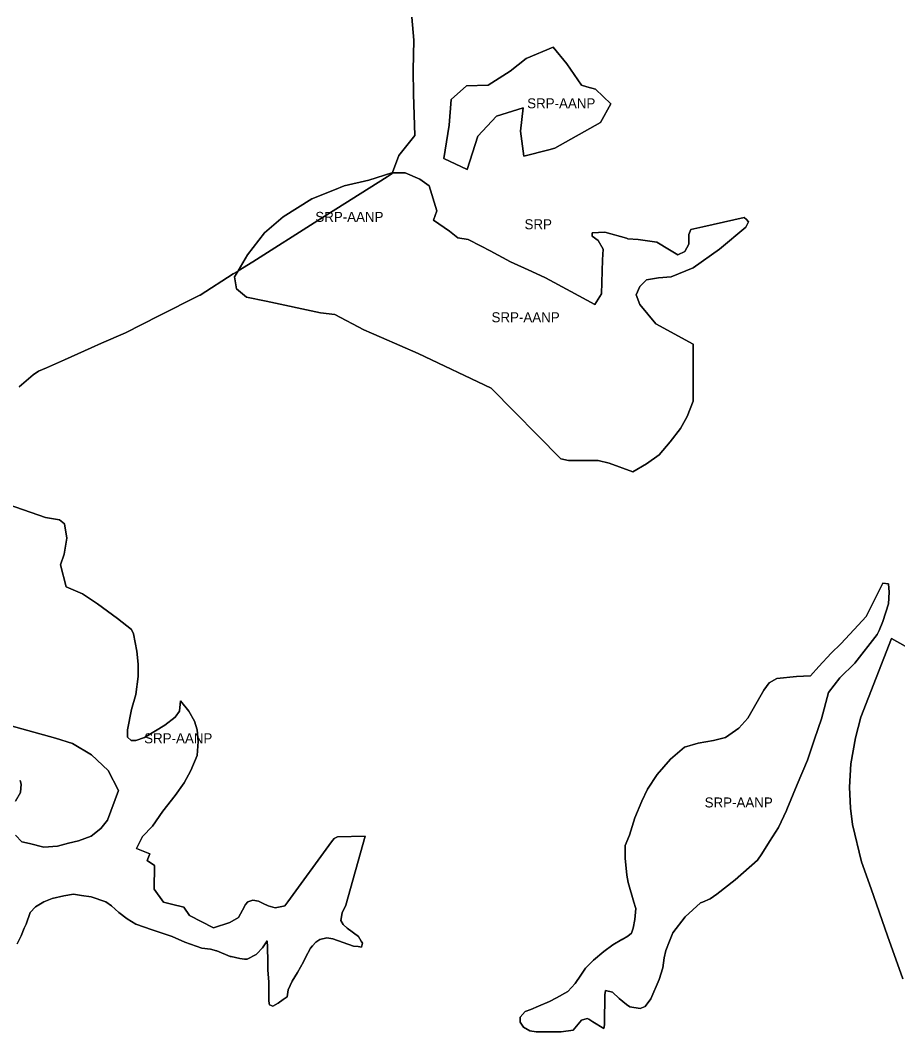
# Model space of a CAD drawing. Extents: x 598968 to 613553, y 4409678 to 4430833.
# Drawn here: x 604005 to 605061, y 4419054 to 4420271 of the extents above; entities that cross this region are included whole.
import ezdxf

# ---------------------------------------------------------------- set-up
doc = ezdxf.new("R2010")
doc.units = 0
for name, color, linetype in [('Nucli Rural', 7, 'Continuous'), ('Sòl Rústic Protegit', 7, 'Continuous'), ('Sòl Rústic Protegit - Alt Nivell de Protecció', 7, 'Continuous')]:
    doc.layers.add(name, color=color, linetype=linetype)

msp = doc.modelspace()

# ---------------------------------------------------------------- linework, layer by layer
at = {"layer": 'Nucli Rural'}
msp.add_lwpolyline([(605086.66, 4419508.7301), (605054.05, 4419527.2401), (605017.1184, 4419432.863), (605010.4212, 4419407.6728), (605004.92, 4419376.5601), (605003.39, 4419348.6024), (605004.54, 4419323.2601), (605006.9552, 4419303.6137), (605017.6511, 4419258.581), (605029.3139, 4419226.1929), (605049.202, 4419169.6187), (605067.6359, 4419117.6672)], dxfattribs=at)
at = {"layer": 'Sòl Rústic Protegit'}
for points in [[(604003.7317, 4419830.1952), (604020.6695, 4419844.6952), (604027.2321, 4419849.1952), (604036.6071, 4419853.1952), (604058.2949, 4419862.6952), (604090.4203, 4419877.1952), (604102.8579, 4419882.6954), (604132.0457, 4419895.1954), (604171.9213, 4419915.6954), (604220.7343, 4419940.1956), (604221.6719, 4419940.6956), (604261.6099, 4419966.1956), (604266.6725, 4419969.1956), (604267.4395, 4419969.6786), (604278.5549, 4419989.0102), (604298.9927, 4420015.5102), (604321.4925, 4420035.0102), (604356.2427, 4420056.5102), (604383.3051, 4420067.5102), (604395.1177, 4420072.0102), (604424.7427, 4420079.0102), (604452.3677, 4420088.0102), (604453.2509, 4420088.0102), (604453.2999, 4420088.196), (604460.8625, 4420108.696), (604480.2379, 4420132.696), (604478.3629, 4420182.6962), (604478.1131, 4420211.1962), (604478.8633, 4420247.6962), (604476.6133, 4420275.1962)], [(604476.6133, 4420275.1962), (604478.8633, 4420247.6962), (604478.1131, 4420211.1962), (604478.3629, 4420182.6962), (604480.2379, 4420132.696), (604460.8625, 4420108.696), (604453.2999, 4420088.196), (604453.2509, 4420088.0102), (604453.6799, 4420088.0102), (604468.6801, 4420088.0102), (604486.0551, 4420080.0102), (604497.3051, 4420072.0102), (604506.4925, 4420042.0102), (604502.4301, 4420031.0102), (604521.8675, 4420017.5102), (604532.0549, 4420009.5102), (604544.3677, 4420007.5102), (604559.9925, 4419999.5102), (604570.9301, 4419994.0102), (604595.4301, 4419980.5102), (604620.9301, 4419969.0102), (604637.3677, 4419961.5102), (604668.0549, 4419945.0102), (604696.6799, 4419929.5102), (604704.8049, 4419942.0102), (604705.8675, 4419983.0102), (604706.8675, 4419996.0102), (604700.7427, 4420006.5102), (604693.5549, 4420011.5102), (604693.5549, 4420015.5102), (604708.9299, 4420016.5102), (604734.9927, 4420009.0102), (604736.4927, 4420008.5102), (604748.8049, 4420007.5102), (604771.2425, 4420004.5102), (604786.6175, 4419995.0102), (604796.8051, 4419989.0102), (604804.9927, 4419993.0102), (604810.1177, 4420002.0102), (604810.1177, 4420013.5102), (604812.1801, 4420019.5102), (604826.8049, 4420023.0102), (604876.5551, 4420034.0102), (604879.2425, 4420031.5102), (604881.6799, 4420029.0102), (604878.6177, 4420022.5102), (604846.9301, 4419996.0102), (604815.2425, 4419973.5102), (604788.6799, 4419962.5102), (604773.3049, 4419961.5102), (604758.9925, 4419959.0102), (604750.8051, 4419951.0102), (604746.7425, 4419941.0102), (604750.8051, 4419929.5102), (604770.2427, 4419906.0102), (604815.2425, 4419881.5102), (604815.2425, 4419813.0102), (604808.0551, 4419794.5102), (604799.8675, 4419780.0102), (604787.6175, 4419764.0102), (604774.3675, 4419748.5102), (604758.9925, 4419737.5102), (604742.6801, 4419728.0102), (604714.0551, 4419738.5102), (604700.7427, 4419741.5102), (604684.3677, 4419741.5102), (604664.9299, 4419741.5102), (604655.7427, 4419743.5102), (604571.9299, 4419828.5102), (604484.0551, 4419870.5102), (604440.0549, 4419889.5102), (604427.8049, 4419895.0102), (604418.6177, 4419899.0102), (604383.8677, 4419917.5102), (604366.4927, 4419919.5102), (604301.0551, 4419933.5102), (604277.5551, 4419938.0102), (604265.3051, 4419948.0102), (604263.2427, 4419962.5102), (604267.0551, 4419969.0102), (604267.4395, 4419969.6786), (604266.6725, 4419969.1956), (604261.6099, 4419966.1956), (604221.6719, 4419940.6956), (604220.7343, 4419940.1956), (604171.9213, 4419915.6954), (604132.0457, 4419895.1954), (604102.8579, 4419882.6954), (604090.4203, 4419877.1952), (604058.2949, 4419862.6952), (604036.6071, 4419853.1952), (604027.2321, 4419849.1952), (604020.6695, 4419844.6952), (604003.7317, 4419830.1952)], [(603943.9927, 4419704.5102), (604035.4301, 4419673.0102), (604052.3677, 4419670.0102), (604058.6175, 4419665.5102), (604061.1177, 4419648.0102), (604057.9927, 4419629.0102), (604053.6177, 4419616.0102), (604060.4927, 4419589.5102), (604079.9299, 4419581.0102), (604098.1175, 4419569.0102), (604122.2425, 4419551.5102), (604139.1801, 4419538.0102), (604141.6801, 4419533.0102), (604145.4301, 4419512.0102), (604147.3051, 4419496.5102), (604147.3051, 4419481.5102), (604144.1801, 4419460.0102), (604139.1801, 4419442.0102), (604134.1175, 4419417.5102), (604134.1175, 4419408.5102), (604138.4927, 4419404.5102), (604144.1801, 4419404.5102), (604154.8051, 4419408.0102), (604179.2425, 4419423.0102), (604191.8049, 4419432.5102), (604196.8051, 4419440.0102), (604198.0549, 4419452.5102), (604208.0551, 4419440.0102), (604214.9299, 4419428.0102), (604218.1177, 4419417.5102), (604219.3677, 4419403.5102), (604218.1177, 4419386.5102), (604210.5551, 4419368.5102), (604202.4301, 4419353.5102), (604191.8049, 4419338.5102), (604176.7425, 4419319.5102), (604164.1799, 4419301.5102), (604152.2425, 4419289.0102), (604145.0551, 4419274.5102), (604161.2427, 4419268.0102), (604157.9299, 4419260.0102), (604166.8677, 4419254.0102), (604166.5551, 4419225.5102), (604177.6801, 4419210.0102), (604187.0551, 4419207.5102), (604202.2425, 4419204.0102), (604208.8677, 4419194.0102), (604237.9299, 4419179.0102), (604257.4301, 4419185.5102), (604267.7427, 4419191.5102), (604272.5549, 4419200.5102), (604276.1801, 4419207.0102), (604279.1799, 4419210.5102), (604285.1799, 4419212.5102), (604292.0551, 4419211.0102), (604297.7425, 4419208.5102), (604303.4301, 4419205.5102), (604311.8677, 4419203.0102), (604321.9927, 4419205.0102), (604323.5551, 4419205.5102), (604327.4299, 4419210.5102), (604379.9299, 4419282.5102), (604382.9301, 4419286.5102), (604386.8675, 4419288.5102), (604420.4301, 4419289.5102), (604397.0549, 4419206.5102), (604392.8051, 4419197.0102), (604391.0551, 4419188.0102), (604393.7427, 4419183.0102), (604398.8049, 4419178.5102), (604412.3051, 4419168.5102), (604415.6175, 4419163.0102), (604417.1177, 4419160.5102), (604415.9299, 4419156.0102), (604411.9927, 4419156.5102), (604406.3051, 4419157.0102), (604381.4927, 4419166.0102), (604374.3049, 4419167.0102), (604365.6175, 4419165.0102), (604360.8051, 4419162.0102), (604356.9301, 4419157.5102), (604354.4927, 4419154.5102), (604348.4925, 4419143.5102), (604346.1177, 4419138.0102), (604338.9301, 4419125.5102), (604332.3051, 4419115.0102), (604327.8049, 4419104.5102), (604326.3051, 4419096.0102), (604321.8051, 4419093.0102), (604315.8051, 4419088.5102), (604309.2425, 4419085.0102), (604305.3051, 4419086.5102), (604304.4299, 4419091.0102), (604304.2427, 4419108.5102), (604304.2427, 4419114.0102), (604303.3675, 4419128.0102), (604303.0551, 4419141.5102), (604302.8051, 4419153.0102), (604302.7427, 4419156.0102), (604302.2427, 4419163.5102), (604296.7425, 4419155.0102), (604290.0549, 4419148.0102), (604289.2427, 4419147.0102), (604278.1799, 4419141.5102), (604275.2427, 4419141.5102), (604269.4299, 4419142.0102), (604259.1177, 4419144.5102), (604258.3677, 4419144.5102), (604257.9927, 4419144.5102), (604241.7427, 4419151.5102), (604241.5551, 4419151.5102), (604234.0551, 4419153.5102), (604223.5551, 4419154.5102), (604203.1801, 4419162.0102), (604187.8677, 4419168.5102), (604163.8675, 4419176.5102), (604144.4927, 4419183.5102), (604133.9927, 4419190.0102), (604123.7427, 4419197.5102), (604115.0551, 4419205.5102), (604108.1799, 4419210.5102), (604090.4927, 4419216.5102), (604079.0551, 4419218.0102), (604069.1801, 4419219.5102), (604057.4925, 4419217.5102), (604043.6801, 4419214.5102), (604033.4927, 4419210.5102), (604023.5551, 4419204.5102), (604017.3049, 4419197.5102), (604012.2427, 4419183.5102), (604009.8051, 4419178.5102), (604006.3051, 4419169.5102), (604005.6177, 4419168.0102), (604001.4301, 4419160.0102)], [(605067.6359, 4419117.6672), (605049.202, 4419169.6187), (605029.3139, 4419226.1929), (605017.6511, 4419258.581), (605006.9552, 4419303.6137), (605004.54, 4419323.2601), (605003.39, 4419348.6024), (605004.92, 4419376.5601), (605010.4212, 4419407.6728), (605017.1184, 4419432.863), (605054.05, 4419527.2401), (605086.66, 4419508.7301)], [(603999.3051, 4419290.5102), (604007.1177, 4419282.5102), (604016.4301, 4419280.5102), (604033.4927, 4419276.0102), (604049.9927, 4419277.5102), (604063.1801, 4419281.0102), (604075.4927, 4419284.0102), (604090.4927, 4419289.5102), (604102.1177, 4419298.5102), (604110.2427, 4419308.5102), (604123.3677, 4419344.5102), (604110.8677, 4419368.5102), (604090.8051, 4419387.5102), (604068.2427, 4419401.0102), (604047.5551, 4419407.5102), (603980.5549, 4419426.0102)], [(604004.9927, 4419356.5102), (604006.2427, 4419352.0102), (604005.6177, 4419342.0102), (603999.3677, 4419331.5102)]]:
    msp.add_lwpolyline(points, dxfattribs=at)
for points in [[(604715.8677, 4420171.0098), (604703.6177, 4420148.5098), (604648.7427, 4420117.5098), (604641.3677, 4420115.5098), (604611.3051, 4420108.0098), (604607.3677, 4420138.0098), (604610.5551, 4420166.0098), (604578.2427, 4420156.0098), (604555.8051, 4420132.0098), (604543.3051, 4420092.0098), (604514.8677, 4420105.0098), (604521.6177, 4420145.0098), (604524.0551, 4420176.0098), (604542.2427, 4420192.5098), (604568.3677, 4420193.5098), (604594.8677, 4420210.0098), (604614.3051, 4420225.5098), (604646.5551, 4420239.0098), (604662.9927, 4420219.0098), (604680.8677, 4420193.5098), (604687.1177, 4420191.5098), (604697.6177, 4420188.5098)], [(604774.4301, 4419117.0102), (604764.1177, 4419093.5102), (604757.2425, 4419084.5102), (604751.2425, 4419082.0102), (604738.8051, 4419084.0102), (604734.9301, 4419087.0102), (604725.9301, 4419094.0102), (604718.2427, 4419101.5102), (604709.6799, 4419103.5102), (604708.8051, 4419098.5102), (604708.8051, 4419088.5102), (604708.3677, 4419074.5102), (604708.3677, 4419062.5102), (604707.4927, 4419058.0102), (604694.2425, 4419066.0102), (604689.4299, 4419069.0102), (604687.3677, 4419070.0102), (604680.9301, 4419068.0102), (604676.6801, 4419063.0102), (604670.6801, 4419056.0102), (604656.1175, 4419054.0102), (604638.5551, 4419054.0102), (604626.1175, 4419054.0102), (604618.4299, 4419055.0102), (604611.1177, 4419059.5102), (604606.8675, 4419065.5102), (604607.0551, 4419071.5102), (604612.9301, 4419078.5102), (604619.7427, 4419081.0102), (604629.1177, 4419085.0102), (604642.3677, 4419090.5102), (604650.6175, 4419095.0102), (604664.1799, 4419102.5102), (604672.9925, 4419112.0102), (604679.8051, 4419122.0102), (604685.6801, 4419130.5102), (604695.1177, 4419140.0102), (604707.4301, 4419150.5102), (604718.3675, 4419158.5102), (604729.2425, 4419165.0102), (604729.5549, 4419165.0102), (604736.6801, 4419169.0102), (604740.9301, 4419172.5102), (604742.9927, 4419178.5102), (604745.1177, 4419189.0102), (604745.5551, 4419198.0102), (604745.9925, 4419202.5102), (604745.6177, 4419203.5102), (604743.8051, 4419210.0102), (604737.0551, 4419233.5102), (604735.3677, 4419242.5102), (604733.1801, 4419263.0102), (604733.1801, 4419278.0102), (604738.3675, 4419290.5102), (604745.0551, 4419311.5102), (604753.4301, 4419331.5102), (604760.1801, 4419346.0102), (604771.9299, 4419363.5102), (604787.8051, 4419382.0102), (604804.6177, 4419396.5102), (604821.3677, 4419401.5102), (604839.8051, 4419404.5102), (604853.9927, 4419408.0102), (604869.9301, 4419419.5102), (604880.8051, 4419431.5102), (604900.1177, 4419465.0102), (604906.8051, 4419474.0102), (604916.0551, 4419479.0102), (604939.4927, 4419481.5102), (604947.9927, 4419482.0102), (604956.3051, 4419482.5102), (604966.3675, 4419493.5102), (604966.5551, 4419493.5102), (604981.4301, 4419509.5102), (604992.8051, 4419521.0102), (605009.1177, 4419538.0102), (605023.3675, 4419554.0102), (605043.4927, 4419594.0102), (605050.1801, 4419593.0102), (605051.0551, 4419583.0102), (605050.1801, 4419569.0102), (605043.4927, 4419548.0102), (605038.8677, 4419537.0102), (605036.8051, 4419532.0102), (605009.9301, 4419497.5102), (604991.4925, 4419480.0102), (604978.1177, 4419462.5102), (604969.6801, 4419430.5102), (604961.3051, 4419406.0102), (604952.9301, 4419381.0102), (604940.3677, 4419351.5102), (604927.8049, 4419321.5102), (604927.3677, 4419320.5102), (604917.7425, 4419300.0102), (604906.8675, 4419283.0102), (604897.6177, 4419268.0102), (604892.6177, 4419260.5102), (604865.7427, 4419237.0102), (604843.4927, 4419219.5102), (604835.6801, 4419214.0102), (604826.3677, 4419210.0102), (604823.9301, 4419209.0102), (604805.6177, 4419192.5102), (604790.6177, 4419173.0102), (604786.8677, 4419163.0102), (604782.0549, 4419152.0102), (604780.3049, 4419143.0102), (604778.6801, 4419131.0102)]]:
    msp.add_lwpolyline(points, close=True, dxfattribs=at)
at = {"layer": 'Sòl Rústic Protegit - Alt Nivell de Protecció'}
for points in [[(604715.8677, 4420171.0098), (604697.6177, 4420188.5098), (604687.1177, 4420191.5098), (604680.8677, 4420193.5098), (604662.9927, 4420219.0098), (604646.5551, 4420239.0098), (604614.3051, 4420225.5098), (604594.8677, 4420210.0098), (604568.3677, 4420193.5098), (604542.2427, 4420192.5098), (604524.0551, 4420176.0098), (604521.6177, 4420145.0098), (604514.8677, 4420105.0098), (604543.3051, 4420092.0098), (604555.8051, 4420132.0098), (604578.2427, 4420156.0098), (604610.5551, 4420166.0098), (604607.3677, 4420138.0098), (604611.3051, 4420108.0098), (604641.3677, 4420115.5098), (604648.7427, 4420117.5098), (604703.6177, 4420148.5098)], [(604267.4395, 4419969.6786), (604267.0551, 4419969.0102), (604263.2427, 4419962.5102), (604265.3051, 4419948.0102), (604277.5551, 4419938.0102), (604301.0551, 4419933.5102), (604366.4927, 4419919.5102), (604383.8677, 4419917.5102), (604418.6177, 4419899.0102), (604427.8049, 4419895.0102), (604440.0549, 4419889.5102), (604484.0551, 4419870.5102), (604571.9299, 4419828.5102), (604655.7427, 4419743.5102), (604664.9299, 4419741.5102), (604684.3677, 4419741.5102), (604700.7427, 4419741.5102), (604714.0551, 4419738.5102), (604742.6801, 4419728.0102), (604758.9925, 4419737.5102), (604774.3675, 4419748.5102), (604787.6175, 4419764.0102), (604799.8675, 4419780.0102), (604808.0551, 4419794.5102), (604815.2425, 4419813.0102), (604815.2425, 4419881.5102), (604770.2427, 4419906.0102), (604750.8051, 4419929.5102), (604746.7425, 4419941.0102), (604750.8051, 4419951.0102), (604758.9925, 4419959.0102), (604773.3049, 4419961.5102), (604788.6799, 4419962.5102), (604815.2425, 4419973.5102), (604846.9301, 4419996.0102), (604878.6177, 4420022.5102), (604881.6799, 4420029.0102), (604879.2425, 4420031.5102), (604876.5551, 4420034.0102), (604826.8049, 4420023.0102), (604812.1801, 4420019.5102), (604810.1177, 4420013.5102), (604810.1177, 4420002.0102), (604804.9927, 4419993.0102), (604796.8051, 4419989.0102), (604786.6175, 4419995.0102), (604771.2425, 4420004.5102), (604748.8049, 4420007.5102), (604736.4927, 4420008.5102), (604734.9927, 4420009.0102), (604708.9299, 4420016.5102), (604693.5549, 4420015.5102), (604693.5549, 4420011.5102), (604700.7427, 4420006.5102), (604706.8675, 4419996.0102), (604705.8675, 4419983.0102), (604704.8049, 4419942.0102), (604696.6799, 4419929.5102), (604668.0549, 4419945.0102), (604637.3677, 4419961.5102), (604620.9301, 4419969.0102), (604595.4301, 4419980.5102), (604570.9301, 4419994.0102), (604559.9925, 4419999.5102), (604544.3677, 4420007.5102), (604532.0549, 4420009.5102), (604521.8675, 4420017.5102), (604502.4301, 4420031.0102), (604506.4925, 4420042.0102), (604497.3051, 4420072.0102), (604486.0551, 4420080.0102), (604468.6801, 4420088.0102), (604453.6799, 4420088.0102), (604453.2509, 4420088.0102), (604453.0133, 4420087.1104), (604446.7853, 4420083.1674), (604363.4083, 4420030.3798), (604285.0179, 4419980.7492)], [(604267.4395, 4419969.6786), (604285.0179, 4419980.7492), (604363.4083, 4420030.3798), (604446.7853, 4420083.1674), (604453.0133, 4420087.1104), (604453.2509, 4420088.0102), (604452.3677, 4420088.0102), (604424.7427, 4420079.0102), (604395.1177, 4420072.0102), (604383.3051, 4420067.5102), (604356.2427, 4420056.5102), (604321.4925, 4420035.0102), (604298.9927, 4420015.5102), (604278.5549, 4419989.0102)], [(604774.4301, 4419117.0102), (604778.6801, 4419131.0102), (604780.3049, 4419143.0102), (604782.0549, 4419152.0102), (604786.8677, 4419163.0102), (604790.6177, 4419173.0102), (604805.6177, 4419192.5102), (604823.9301, 4419209.0102), (604826.3677, 4419210.0102), (604835.6801, 4419214.0102), (604843.4927, 4419219.5102), (604865.7427, 4419237.0102), (604892.6177, 4419260.5102), (604897.6177, 4419268.0102), (604906.8675, 4419283.0102), (604917.7425, 4419300.0102), (604927.3677, 4419320.5102), (604927.8049, 4419321.5102), (604940.3677, 4419351.5102), (604952.9301, 4419381.0102), (604961.3051, 4419406.0102), (604969.6801, 4419430.5102), (604978.1177, 4419462.5102), (604991.4925, 4419480.0102), (605009.9301, 4419497.5102), (605036.8051, 4419532.0102), (605038.8677, 4419537.0102), (605043.4927, 4419548.0102), (605050.1801, 4419569.0102), (605051.0551, 4419583.0102), (605050.1801, 4419593.0102), (605043.4927, 4419594.0102), (605023.3675, 4419554.0102), (605009.1177, 4419538.0102), (604992.8051, 4419521.0102), (604981.4301, 4419509.5102), (604966.5551, 4419493.5102), (604966.3675, 4419493.5102), (604956.3051, 4419482.5102), (604947.9927, 4419482.0102), (604939.4927, 4419481.5102), (604916.0551, 4419479.0102), (604906.8051, 4419474.0102), (604900.1177, 4419465.0102), (604880.8051, 4419431.5102), (604869.9301, 4419419.5102), (604853.9927, 4419408.0102), (604839.8051, 4419404.5102), (604821.3677, 4419401.5102), (604804.6177, 4419396.5102), (604787.8051, 4419382.0102), (604771.9299, 4419363.5102), (604760.1801, 4419346.0102), (604753.4301, 4419331.5102), (604745.0551, 4419311.5102), (604738.3675, 4419290.5102), (604733.1801, 4419278.0102), (604733.1801, 4419263.0102), (604735.3677, 4419242.5102), (604737.0551, 4419233.5102), (604743.8051, 4419210.0102), (604745.6177, 4419203.5102), (604745.9925, 4419202.5102), (604745.5551, 4419198.0102), (604745.1177, 4419189.0102), (604742.9927, 4419178.5102), (604740.9301, 4419172.5102), (604736.6801, 4419169.0102), (604729.5549, 4419165.0102), (604729.2425, 4419165.0102), (604718.3675, 4419158.5102), (604707.4301, 4419150.5102), (604695.1177, 4419140.0102), (604685.6801, 4419130.5102), (604679.8051, 4419122.0102), (604672.9925, 4419112.0102), (604664.1799, 4419102.5102), (604650.6175, 4419095.0102), (604642.3677, 4419090.5102), (604629.1177, 4419085.0102), (604619.7427, 4419081.0102), (604612.9301, 4419078.5102), (604607.0551, 4419071.5102), (604606.8675, 4419065.5102), (604611.1177, 4419059.5102), (604618.4299, 4419055.0102), (604626.1175, 4419054.0102), (604638.5551, 4419054.0102), (604656.1175, 4419054.0102), (604670.6801, 4419056.0102), (604676.6801, 4419063.0102), (604680.9301, 4419068.0102), (604687.3677, 4419070.0102), (604689.4299, 4419069.0102), (604694.2425, 4419066.0102), (604707.4927, 4419058.0102), (604708.3677, 4419062.5102), (604708.3677, 4419074.5102), (604708.8051, 4419088.5102), (604708.8051, 4419098.5102), (604709.6799, 4419103.5102), (604718.2427, 4419101.5102), (604725.9301, 4419094.0102), (604734.9301, 4419087.0102), (604738.8051, 4419084.0102), (604751.2425, 4419082.0102), (604757.2425, 4419084.5102), (604764.1177, 4419093.5102)]]:
    msp.add_lwpolyline(points, close=True, dxfattribs=at)
for points in [[(604001.4301, 4419160.0102), (604005.6177, 4419168.0102), (604006.3051, 4419169.5102), (604009.8051, 4419178.5102), (604012.2427, 4419183.5102), (604017.3049, 4419197.5102), (604023.5551, 4419204.5102), (604033.4927, 4419210.5102), (604043.6801, 4419214.5102), (604057.4925, 4419217.5102), (604069.1801, 4419219.5102), (604079.0551, 4419218.0102), (604090.4927, 4419216.5102), (604108.1799, 4419210.5102), (604115.0551, 4419205.5102), (604123.7427, 4419197.5102), (604133.9927, 4419190.0102), (604144.4927, 4419183.5102), (604163.8675, 4419176.5102), (604187.8677, 4419168.5102), (604203.1801, 4419162.0102), (604223.5551, 4419154.5102), (604234.0551, 4419153.5102), (604241.5551, 4419151.5102), (604241.7427, 4419151.5102), (604257.9927, 4419144.5102), (604258.3677, 4419144.5102), (604259.1177, 4419144.5102), (604269.4299, 4419142.0102), (604275.2427, 4419141.5102), (604278.1799, 4419141.5102), (604289.2427, 4419147.0102), (604290.0549, 4419148.0102), (604296.7425, 4419155.0102), (604302.2427, 4419163.5102), (604302.7427, 4419156.0102), (604302.8051, 4419153.0102), (604303.0551, 4419141.5102), (604303.3675, 4419128.0102), (604304.2427, 4419114.0102), (604304.2427, 4419108.5102), (604304.4299, 4419091.0102), (604305.3051, 4419086.5102), (604309.2425, 4419085.0102), (604315.8051, 4419088.5102), (604321.8051, 4419093.0102), (604326.3051, 4419096.0102), (604327.8049, 4419104.5102), (604332.3051, 4419115.0102), (604338.9301, 4419125.5102), (604346.1177, 4419138.0102), (604348.4925, 4419143.5102), (604354.4927, 4419154.5102), (604356.9301, 4419157.5102), (604360.8051, 4419162.0102), (604365.6175, 4419165.0102), (604374.3049, 4419167.0102), (604381.4927, 4419166.0102), (604406.3051, 4419157.0102), (604411.9927, 4419156.5102), (604415.9299, 4419156.0102), (604417.1177, 4419160.5102), (604415.6175, 4419163.0102), (604412.3051, 4419168.5102), (604398.8049, 4419178.5102), (604393.7427, 4419183.0102), (604391.0551, 4419188.0102), (604392.8051, 4419197.0102), (604397.0549, 4419206.5102), (604420.4301, 4419289.5102), (604386.8675, 4419288.5102), (604382.9301, 4419286.5102), (604379.9299, 4419282.5102), (604327.4299, 4419210.5102), (604323.5551, 4419205.5102), (604321.9927, 4419205.0102), (604311.8677, 4419203.0102), (604303.4301, 4419205.5102), (604297.7425, 4419208.5102), (604292.0551, 4419211.0102), (604285.1799, 4419212.5102), (604279.1799, 4419210.5102), (604276.1801, 4419207.0102), (604272.5549, 4419200.5102), (604267.7427, 4419191.5102), (604257.4301, 4419185.5102), (604237.9299, 4419179.0102), (604208.8677, 4419194.0102), (604202.2425, 4419204.0102), (604187.0551, 4419207.5102), (604177.6801, 4419210.0102), (604166.5551, 4419225.5102), (604166.8677, 4419254.0102), (604157.9299, 4419260.0102), (604161.2427, 4419268.0102), (604145.0551, 4419274.5102), (604152.2425, 4419289.0102), (604164.1799, 4419301.5102), (604176.7425, 4419319.5102), (604191.8049, 4419338.5102), (604202.4301, 4419353.5102), (604210.5551, 4419368.5102), (604218.1177, 4419386.5102), (604219.3677, 4419403.5102), (604218.1177, 4419417.5102), (604214.9299, 4419428.0102), (604208.0551, 4419440.0102), (604198.0549, 4419452.5102), (604196.8051, 4419440.0102), (604191.8049, 4419432.5102), (604179.2425, 4419423.0102), (604154.8051, 4419408.0102), (604144.1801, 4419404.5102), (604138.4927, 4419404.5102), (604134.1175, 4419408.5102), (604134.1175, 4419417.5102), (604139.1801, 4419442.0102), (604144.1801, 4419460.0102), (604147.3051, 4419481.5102), (604147.3051, 4419496.5102), (604145.4301, 4419512.0102), (604141.6801, 4419533.0102), (604139.1801, 4419538.0102), (604122.2425, 4419551.5102), (604098.1175, 4419569.0102), (604079.9299, 4419581.0102), (604060.4927, 4419589.5102), (604053.6177, 4419616.0102), (604057.9927, 4419629.0102), (604061.1177, 4419648.0102), (604058.6175, 4419665.5102), (604052.3677, 4419670.0102), (604035.4301, 4419673.0102), (603943.9927, 4419704.5102)], [(603980.5549, 4419426.0102), (604047.5551, 4419407.5102), (604068.2427, 4419401.0102), (604090.8051, 4419387.5102), (604110.8677, 4419368.5102), (604123.3677, 4419344.5102), (604110.2427, 4419308.5102), (604102.1177, 4419298.5102), (604090.4927, 4419289.5102), (604075.4927, 4419284.0102), (604063.1801, 4419281.0102), (604049.9927, 4419277.5102), (604033.4927, 4419276.0102), (604016.4301, 4419280.5102), (604007.1177, 4419282.5102), (603999.3051, 4419290.5102)], [(603999.3677, 4419331.5102), (604005.6177, 4419342.0102), (604006.2427, 4419352.0102), (604004.9927, 4419356.5102)]]:
    msp.add_lwpolyline(points, dxfattribs=at)

# ---------------------------------------------------------------- texts
at = {"layer": 'Sòl Rústic Protegit'}
msp.add_text('SRP', height=12, dxfattribs=at).set_placement((604612.1964, 4420019.9465))
at = {"layer": 'Sòl Rústic Protegit - Alt Nivell de Protecció'}
for p in [(604615.3677, 4420165.5098), (604360.3452, 4420028.8444), (604572.4613, 4419908.0102), (604154.3504, 4419401.2602), (604828.9613, 4419324.0102)]:
    msp.add_text('SRP-AANP', height=12, dxfattribs=at).set_placement(p)

doc.saveas('drawing.dxf')
